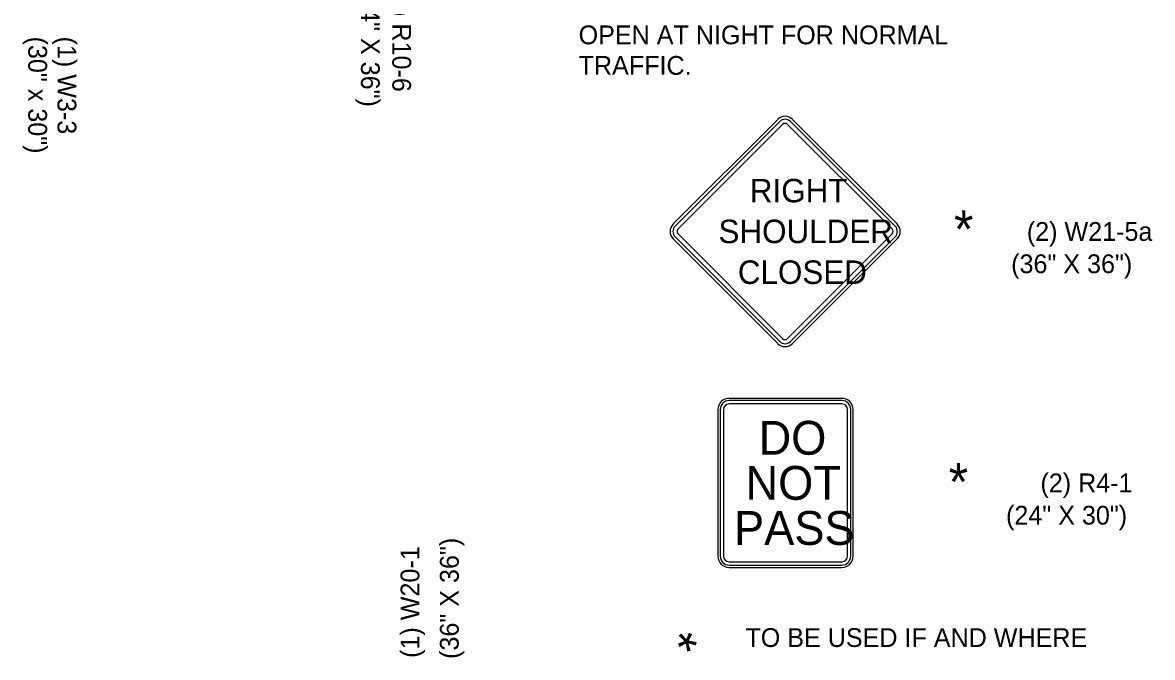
# Model space of a CAD drawing. Extents: x 1927831 to 1930787, y 596452 to 597699.
# Drawn here: x 1928492.8 to 1928853.8, y 597193.2 to 597396 of the extents above; entities that cross this region are included whole.
import ezdxf

# ---------------------------------------------------------------- set-up
doc = ezdxf.new("R2010")
doc.units = 0
for name, color, linetype in [('Default', 7, 'Continuous'), ('P_TC_Signs_Permanent', 7, 'Continuous'), ('P_TC_Signs_Temporary', 7, 'Continuous'), ('R_Border', 7, 'Continuous'), ('S_AREA_CALC', 7, 'Continuous')]:
    doc.layers.add(name, color=color, linetype=linetype)

msp = doc.modelspace()

# ---------------------------------------------------------------- linework, layer by layer
at = {"layer": 'P_TC_Signs_Permanent'}
for p, q in [((1928754.55, 597275.97), (1928718.55, 597275.97)), ((1928754.55, 597275.25), (1928718.55, 597275.25)), ((1928754.55, 597274.17), (1928718.55, 597274.17)), ((1928714.95, 597272.37), (1928714.95, 597225.57)), ((1928715.67, 597272.37), (1928715.67, 597225.57)), ((1928716.75, 597272.37), (1928716.75, 597225.57)), ((1928756.35, 597225.57), (1928756.35, 597272.37)), ((1928757.43, 597225.57), (1928757.43, 597272.37)), ((1928758.15, 597225.57), (1928758.15, 597272.37)), ((1928718.55, 597223.77), (1928754.55, 597223.77)), ((1928718.55, 597222.69), (1928754.55, 597222.69)), ((1928718.55, 597221.97), (1928754.55, 597221.97))]:
    msp.add_line(p, q, dxfattribs=at)
for centre, radius, start, end in [((1928718.55, 597272.37), 3.6, 90, 180), ((1928718.55, 597272.37), 2.88, 90, 180), ((1928718.55, 597272.37), 1.8, 90, 180), ((1928754.55, 597272.37), 3.6, 360, 90), ((1928754.55, 597272.37), 2.88, 360, 90), ((1928754.55, 597272.37), 1.8, 360, 90), ((1928718.55, 597225.57), 3.6, 180, 270), ((1928718.55, 597225.57), 2.88, 180, 270), ((1928718.55, 597225.57), 1.8, 180, 270), ((1928754.55, 597225.57), 3.6, 270, 360), ((1928754.55, 597225.57), 2.88, 270, 360), ((1928754.55, 597225.57), 1.8, 270, 360)]:
    msp.add_arc(centre, radius, start, end, dxfattribs=at)
at = {"layer": 'P_TC_Signs_Temporary'}
for p, q in [((1928700.64, 597331.67), (1928734.05, 597365.08)), ((1928701.3, 597331), (1928734.71, 597364.41)), ((1928702.23, 597330.07), (1928735.64, 597363.49)), ((1928737.23, 597363.49), (1928770.64, 597330.07)), ((1928738.16, 597364.41), (1928771.57, 597331)), ((1928738.82, 597365.08), (1928772.23, 597331.67)), ((1928734.05, 597293.48), (1928700.64, 597326.89)), ((1928734.71, 597294.14), (1928701.3, 597327.56)), ((1928735.64, 597295.07), (1928702.23, 597328.48)), ((1928770.64, 597328.48), (1928737.23, 597295.07)), ((1928771.57, 597327.56), (1928738.16, 597294.14)), ((1928772.23, 597326.89), (1928738.82, 597293.48))]:
    msp.add_line(p, q, dxfattribs=at)
for centre, radius, start, end in [((1928736.43, 597362.69), 3.38, 45, 135), ((1928736.43, 597362.69), 2.44, 45, 135), ((1928736.43, 597362.69), 1.13, 45, 135), ((1928703.02, 597329.28), 3.37, 135, 225), ((1928703.02, 597329.28), 2.44, 135, 225), ((1928769.84, 597329.28), 2.44, 315, 45), ((1928769.84, 597329.28), 3.37, 315, 45), ((1928703.02, 597329.28), 1.12, 135, 225), ((1928769.84, 597329.28), 1.12, 315, 45), ((1928736.43, 597295.87), 1.13, 225, 315), ((1928736.43, 597295.87), 3.38, 225, 315), ((1928736.43, 597295.87), 2.44, 225, 315)]:
    msp.add_arc(centre, radius, start, end, dxfattribs=at)

# ---------------------------------------------------------------- texts
at = {"layer": 'Default'}
for s, p in [('(36" X 36")', (1928632.12, 597192.73)), ('(1) W20-1', (1928619.55, 597193.06))]:
    msp.add_text(s, height=6, rotation=90, dxfattribs=at).set_placement(p)
at = {"layer": 'P_TC_Signs_Permanent'}
for s, rotation, p in [('DO', 360, (1928727.95, 597257.97)), ('NOT', 359.9596, (1928723.77, 597243.58)), ('PASS', 360, (1928720.1, 597229.17))]:
    msp.add_text(s, height=10.8, rotation=rotation, dxfattribs=at).set_placement(p)
at = {"layer": 'P_TC_Signs_Temporary'}
for s, p in [('RIGHT', (1928725.16, 597338.58)), ('SHOULDER', (1928715.14, 597325.56)), ('CLOSED', (1928721.32, 597312.53))]:
    msp.add_text(s, height=7.5, rotation=360, dxfattribs=at).set_placement(p)
at = {"layer": 'R_Border'}
for s, height, rotation, p in [('(24" X 36")', 5.9996, 270, (1928600.89, 597407.77)), ('(1) R10-6', 6, 270, (1928610.9, 597407.77)), ('OPEN AT NIGHT FOR NORMAL ', 6, 360, (1928670.44, 597389.08)), ('(30" x 30")', 5.9996, 270, (1928494.57, 597391.54)), ('(1) W3-3', 6, 270, (1928503.93, 597391.54)), ('TRAFFIC.', 6, 360, (1928670.44, 597379.33)), ('(2) W21-5a', 6, 360, (1928813.67, 597326.28)), ('(36" X 36")', 6, 360, (1928808.66, 597315.96)), ('(2) R4-1', 6, 360, (1928818.02, 597245.97)), ('(24" X 30")', 6, 360, (1928807.02, 597235.65)), ('*', 12, 45, (1928709.04, 597189.82)), ('TO BE USED IF AND WHERE', 6, 360, (1928723.75, 597196.56))]:
    msp.add_text(s, height=height, rotation=rotation, dxfattribs=at).set_placement(p)
at = {"layer": 'S_AREA_CALC'}
for p in [(1928790.38, 597324.03), (1928788.69, 597243.29)]:
    msp.add_text('*', height=12, rotation=360, dxfattribs=at).set_placement(p)

doc.saveas('drawing.dxf')
